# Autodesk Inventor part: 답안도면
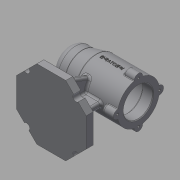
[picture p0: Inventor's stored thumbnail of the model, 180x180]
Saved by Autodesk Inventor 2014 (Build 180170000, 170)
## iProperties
Created: 2021-01
Part Number: 답안도면
Material: Generic
Document SubType Name: Modeling
Designer: kh
Density: 1 g/cm^3
Appearance: Default
Mass: 232.753 g
Surface Area: 617.741 cm^2
Volume: 232.753 cm^3
Author: kh
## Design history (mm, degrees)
sketch "Sketch1"
  geometry: L1 (0, 0)-(100, 0); L2 (100, 0)-(100, 30); L3 (100, 30)-(40, 30); L4 (40, 30)-(20, 25); L5 (20, 25)-(0, 25); L6 (0, 25)-(0, 0); L7 (100, 21)-(85, 21); L8 (85, 21)-(85, 24); L9 (85, 24)-(43, 24); L10 (43, 24)-(43, 21); L11 (43, 21)-(31, 21); L12 (31, 21)-(31, 17.5); L13 (31, 17.5)-(13, 17.5); L14 (13, 17.5)-(13, 16); L15 (13, 16)-(9, 16); L16 (9, 16)-(9, 10.5); L17 (9, 10.5)-(6, 10.5); L18 (6, 10.5)-(6, 0)
  constraints: 36 end point, 11 parallel, 4 perpendicular, 2 point on line, 1 collinear, 1 horizontal
  dimensions: "d0" = 100 distance of L1.start L1.end; "d1" = 60 diameter of L3 L1; "d2" = 50 diameter of L5 L1; "d3" = 20 distance of L4.end L5.end; "d4" = 40 horizontal distance of L5.end L3.end; "d6" = 42 diameter of L7 L1; "d7" = 48 diameter of L9 L1; "d8" = 42 diameter of L11 L1; "d9" = 35 diameter of L13 L1; "d10" = 32 diameter of L15 L1; "d11" = 21 diameter of L17 L1; "d12" = 3 distance of L16.end L17.end; "d13" = 4 distance of L14.end L15.end; "d14" = 18 distance of L12.end L13.end; "d15" = 12 distance of L10.end L11.end; "d16" = 42 distance of L8.end L9.end; "d17" = 15 distance of L7.start L7.end
revolve "Revolution1" stored, may be unused: angle "d5" = 90 deg
revolve "Revolution2" stored, may be unused: angle "d18" = 90 deg
workplane "Work Plane1"
sketch "Sketch2" dims "d20" = 100
  geometry: L1 (-100, 30)-(-100, -30) reference; L2 (0, 25)-(0, -25) reference; L3 (-40, 30)-(-40, -30) reference; L4 (-100, 30)-(-100, -30) reference; L5 (-40, -30)-(-100, -30) reference; L6 (-40, 30)-(-100, 30) reference; L7 (0, 0)-(-50, 0); L8 (-70.711, -50)-(-100, -20.711); L9 (-100, -20.711)-(-100, 20.711); L10 (-100, 20.711)-(-70.711, 50); L11 (-70.711, 50)-(-29.289, 50); L12 (-29.289, 50)-(0, 20.711); L13 (0, 20.711)-(0, -20.711); L14 (0, -20.711)-(-29.289, -50); L15 (-29.289, -50)-(-70.711, -50); L16 (-50, 0)-(-50, -50)
  constraints: 20 end point, 1 coincident, 1 midpoint, 1 parallel, 1 vertical, 1 vertical alignment, 19 other
  dimensions: "d21" = 50 distance of L7.start L7.end
extrude "Extrusion1" join sketch "Sketch2" distance "d22" = 10; taper "d23" = 0 deg
sketch "Sketch3"
  geometry: L1 (100, 20.711)-(100, -20.711) reference; L2 (100, -20.711)-(70.711, -50) reference; L3 (70.711, -50)-(29.289, -50) reference; L4 (29.289, -50)-(0, -20.711) reference; L5 (0, -20.711)-(0, 20.711) reference; L6 (0, 20.711)-(29.289, 50) reference; L7 (29.289, 50)-(70.711, 50) reference; L8 (70.711, 50)-(100, 20.711) reference; L9 (62, 4)-(77, 4); L10 (77, 4)-(77, -4); L11 (77, -4)-(62, -4); L12 (62, -4)-(62, 4); L13 (0, 0)-(77, 0)
  constraints: 10 end point, 2 horizontal, 2 parallel, 1 midpoint, 1 perpendicular
  dimensions: "d24" = 8 distance of L9.end L10.end; "d25" = 23 distance from line of L1 L13.end; "d26" = 15 distance of L9.start L9.end
extrude "Extrusion2" join sketch "Sketch3" stored distance "d27" = 0; taper "d28" = 0 deg
sketch "Sketch4"
  geometry: L1 (0, -25)-(0, 25) reference; L2 (0, 25)-(20, 25) reference; L3 (20, 25)-(40, 30) reference; L4 (40, 30)-(100, 30) reference; L5 (100, 30)-(100, 21) reference; L6 (100, 21)-(85, 21) reference; L7 (85, 21)-(85, 24) reference; L8 (85, 24)-(43, 24) reference; L9 (43, 24)-(43, 21) reference; L10 (43, 21)-(31, 21) reference; L11 (31, 21)-(31, 17.5) reference; L12 (31, 17.5)-(13, 17.5) reference; L13 (13, 17.5)-(13, 16) reference; L14 (13, 16)-(9, 16) reference; L15 (9, 16)-(9, 10.5) reference; L16 (9, 10.5)-(6, 10.5) reference; L17 (6, 10.5)-(6, -10.5) reference; L18 (6, -10.5)-(9, -10.5) reference; L19 (9, -10.5)-(9, -16) reference; L20 (9, -16)-(13, -16) reference; L21 (13, -16)-(13, -17.5) reference; L22 (13, -17.5)-(31, -17.5) reference; L23 (31, -17.5)-(31, -21) reference; L24 (31, -21)-(43, -21) reference; L25 (43, -21)-(43, -24) reference; L26 (43, -24)-(85, -24) reference; L27 (85, -24)-(85, -21) reference; L28 (85, -21)-(100, -21) reference; L29 (100, -21)-(100, -30) reference; L30 (100, -30)-(77, -30) reference; L31 (77, -30)-(77, -65) reference; L32 (77, -65)-(100, -65) reference; L33 (100, -65)-(100, -75) reference; L34 (100, -75)-(0, -75) reference; L35 (0, -75)-(0, -65) reference; L36 (0, -65)-(62, -65) reference; L37 (62, -65)-(62, -30) reference; L38 (62, -30)-(40, -30) reference; L39 (40, -30)-(20, -25) reference; L40 (20, -25)-(0, -25) reference; L41 (23, -65)-(27.653, -41.063); 1 further point
  constraints: 2 end point, 1 point on line
  dimensions: "d29" = 23 distance of L41.start L35.end; "d30" = 101 deg angle of L36 L41
feature "Rib1" sketch "Sketch4" dims "d31" = 1, "d32" = 8, "d33" = 0, "d34" = 0, "d35" = 1, "d36" = 1
workplane "Work Plane2"
sketch "Sketch5"
  geometry: L1 (-65, 50)-(-65, 4) reference; L2 (-65, 4)-(-29.732, 4) reference; L3 (-29.732, -4)-(-65, -4) reference; L4 (-65, -4)-(-65, -50) reference; L5 (-65, -50)-(-75, -50) reference; L6 (-75, -50)-(-75, 50) reference; L7 (-75, 50)-(-65, 50) reference; L8 (-65, 35)-(-42.933, 26.968); L9 (-65, -35)-(-36.274, -24.545); C1 r 24 at (0, 0) reference; A1 r 30 centre (0, 0) between (-29.732, -4) and (-29.732, 4) reference; 1 further point
  constraints: 4 end point, 2 point on line
  dimensions: "d37" = 15 distance of L8.start L1.start; "d38" = 15 distance of L4.end L9.start; "d39" = 110 deg angle of L8 L1; "d40" = 110 deg angle of L4 L9
  node "Project Cut Edges3"
feature "Rib2" dims "d41" = 1, "d42" = 8, "d43" = 0, "d44" = 0, "d45" = 1, "d46" = 1
feature "Rib3" dims "d47" = 1, "d48" = 8, "d49" = 0, "d50" = 0, "d51" = 1, "d52" = 1
sketch "Sketch6"
  geometry: L1 (0, 0)-(0, 30); C1 r 21 at (0, 0) reference; C2 r 6 at (0, 30); 2 further points
  constraints: 2 end point, 1 centre point, 1 vertical, 1 vertical alignment, 1 other
  dimensions: "d53" = 12 diameter of C2
extrude "Extrusion3" join sketch "Sketch6" distance "d54" = 16; taper "d55" = 0 deg
hole "Hole1" diameter "d58" = 3.242; stored, may be unused: countersink angle "d62" = 90 deg, drill point angle "d64" = 118 deg; dims "d56" = 10, "d57" = 10, "d59" = 8, "d60" = 4, "d61" = 2, "d63" = 10
pattern_circular "Circular Pattern1" dims angle "d66" = 360 deg
sketch "Sketch7"
  geometry: L1 (70.711, -50)-(29.289, -50) reference; L2 (29.289, -50)-(0, -20.711) reference; L3 (0, -20.711)-(0, 20.711) reference; L4 (0, 20.711)-(29.289, 50) reference; L5 (29.289, 50)-(70.711, 50) reference; L6 (70.711, 50)-(100, 20.711) reference; L7 (100, 20.711)-(100, -20.711) reference; L8 (100, -20.711)-(70.711, -50) reference; L9 (0, 0)-(100, 0); L10 (50, 50)-(50, -50); L11 (14.645, -35.355)-(85.355, 35.355); L12 (14.645, 35.355)-(85.355, -35.355); C1 r 4.5 at (14.645, -35.355); C2 r 4.5 at (85.355, 35.355); C3 r 4.5 at (85.355, -35.355); C4 r 4.5 at (14.645, 35.355); 2 further points
  constraints: 9 midpoint, 8 end point, 4 centre point, 4 coincident, 1 point on line
  dimensions: "d69" = 9 diameter of C1; "d70" = 9 diameter of C2; "d71" = 9 diameter of C3; "d73" = 9 diameter of C4
extrude "Extrusion4" cut sketch "Sketch7" stored distance "d74" = 16; taper "d75" = 0 deg
fillet "Fillet1" dims "d76" = 10
fillet "Fillet2" dims "d77" = 3
fillet "Fillet3" dims "d78" = 3
fillet "Fillet4" dims "d79" = 3
fillet "Fillet5" dims "d80" = 3
fillet "Fillet6" dims "d81" = 3
fillet "Fillet7" dims "d82" = 1
fillet "Fillet8" dims "d83" = 1
fillet "Fillet9" dims "d84" = 3
fillet "Fillet10" dims "d85" = 0.3
chamfer "Chamfer1" distance "d86" = 1; stored, may be unused: second distance "d87" = 2, angle "d88" = 45 deg
workplane "Work Plane3"
sketch "Sketch8"
  geometry: L1 (-24.592, 2.402)-(8.592, 2.402); L2 (8.592, 2.402)-(8.592, -2.402); L3 (8.592, -2.402)-(-24.592, -2.402); L4 (-24.592, -2.402)-(-24.592, 2.402); L5 (-24.592, 0)-(8.592, 0); L6 (-8, 2.402)-(-8, -2.402); L7 (30, 6.771)-(30, 29.226) reference; 1 further point
  constraints: 4 end point, 4 midpoint, 1 horizontal alignment, 2 other
  dimensions: "d89" = 38 distance between parallel lines of L7 L6
emboss "Emboss1" sketch "Sketch8" dims "d0" = 100, "d1" = 60, "d2" = 50, "d3" = 20, "d4" = 40, "d6" = 42, "d7" = 48, "d8" = 42, "d9" = 35, "d10" = 32, "d11" = 21, "d12" = 3, "d13" = 4, "d14" = 18, "d15" = 12, "d16" = 42, "d17" = 15, "d90" = 0.5, "d91" = 0
fillet "Fillet11" dims "d92" = 3
body "Solid1"
node "Projected Loop1"
node "Projected Loop2"
node "Projected Loop3"
node "Project Cut Edges1"
node "Project Cut Edges2"
other parameters: "d19" = -75
